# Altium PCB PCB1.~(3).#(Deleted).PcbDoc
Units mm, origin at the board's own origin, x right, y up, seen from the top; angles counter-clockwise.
Board outline 33.19 x 35.73 mm, 2 copper layers (Top Layer, Bottom Layer); 37 components, 26 nets, 150 pads, 0 vias.
Unrouted connection lines stored in the file: 81.
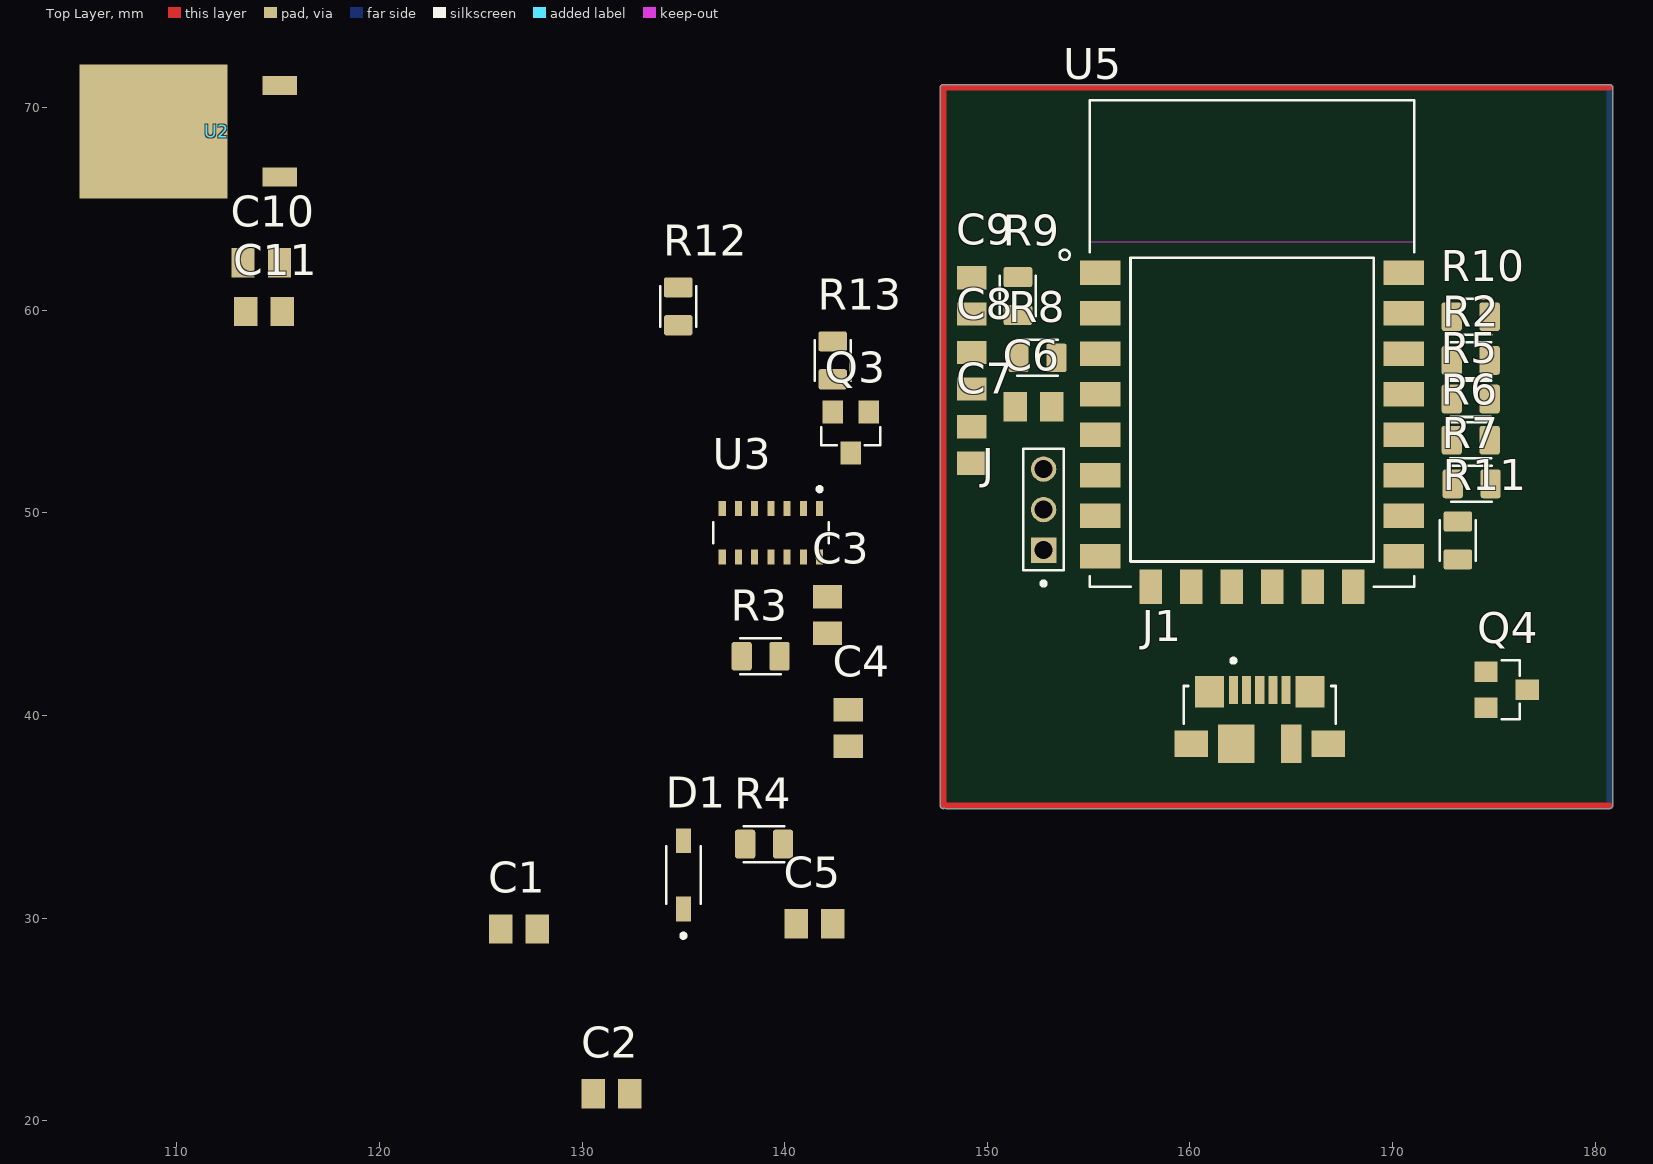
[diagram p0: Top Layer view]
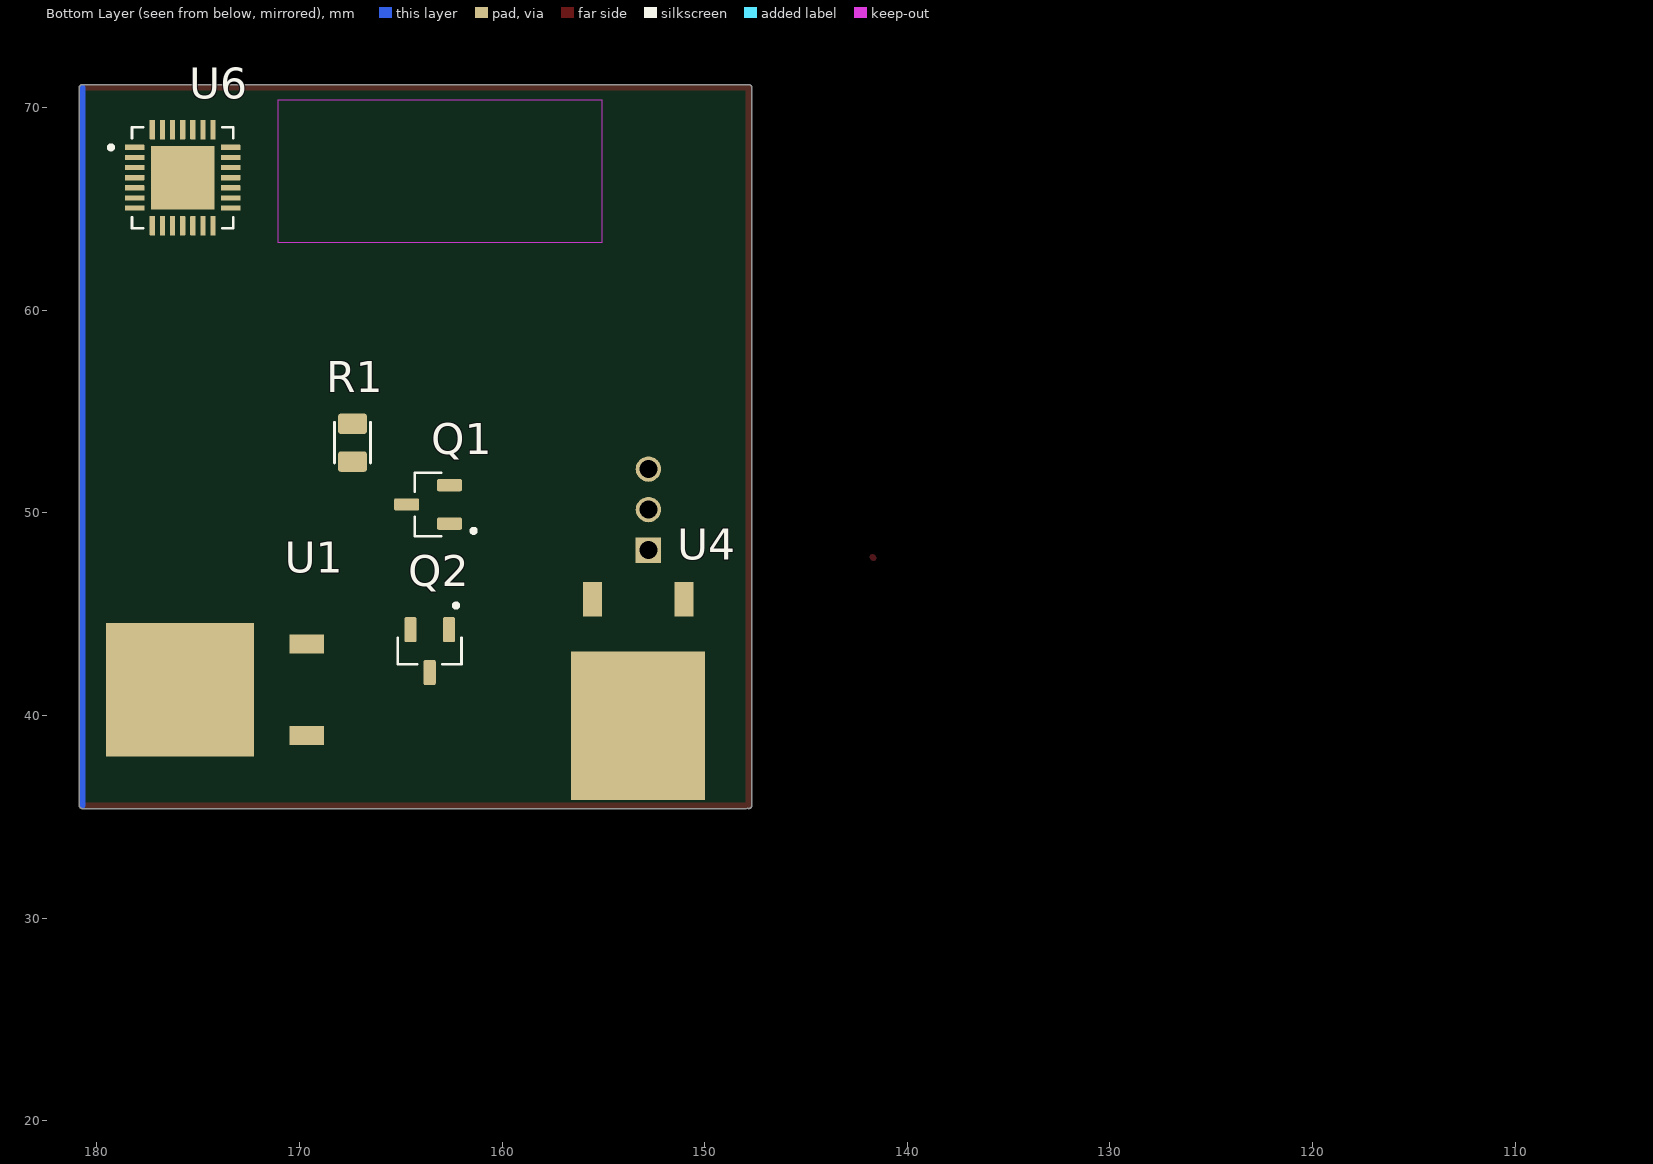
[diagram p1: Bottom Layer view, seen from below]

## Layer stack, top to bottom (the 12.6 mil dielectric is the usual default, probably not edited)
Top Solder: solder mask 0.0102, Solder Resist, Dk 3.5
Top Layer: signal copper 0.0356
Dielectric 1: dielectric 0.32, FR-4, Dk 4.8
Bottom Layer: signal copper 0.0356
Bottom Solder: solder mask 0.0102, Solder Resist, Dk 3.5

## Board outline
147.678,35.56 147.678,70.434 147.678,70.993 cw(c147.828,70.993) 147.828,71.143 180.721,71.143 cw(c180.721,70.993) 180.871,70.993 180.871,35.56 cw(c180.721,35.56) 180.721,35.41 147.955,35.41 147.892,35.424 cw(c147.828,35.56)

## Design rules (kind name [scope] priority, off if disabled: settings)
Clearance [All] p1: gap=0.254 ignorepadtopadclearanceinfootprint=FALSE except(0: Arc-Hole Track-Hole SMDPad-Hole THPad-Hole Via-Hole Fill-Hole Poly-Hole Region-Hole Text-Hole)
PolygonConnect [All] p1: connectstyle=Relief reliefconductorwidth=0.254 reliefentries=4 polygonreliefangle="90 Angle" airgapwidth=0.254
RoutingVias [All] p1: holewidth=0.711 width=1.27 viastyle="Through Hole" minholewidth=0.711 minwidth=1.27 maxholewidth=0.711 maxwidth=1.27
SolderMaskExpansion [All] p1: expansion=0.102 istentingtop=FALSE
Width [All] p1: maxlimit=0.254 minlimit=0.254 preferedwidth=0.254
30 further rules are at their usual default settings.

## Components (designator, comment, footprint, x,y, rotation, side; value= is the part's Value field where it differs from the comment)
C1 "1uF" CAPC2012X140N 126.884,29.464 r180 top
C2 "47uF" CAPC2012X140N 131.456,21.336 r0 top
C3 "0.1uF" CAPC2012X140N 142.113,44.969 r270 top
C4 "1uF" CAPC2012X140N 143.129,39.381 r90 top
C5 "10uF" CAPC2012X140N 141.478,29.718 r180 top
C6 "10uF" CAPC2012X140N 152.284,55.245 r180 top
C7 "10uF" CAPC2012X140N 149.225,53.351 r270 top
C8 "100nF" CAPC2012X140N 149.225,57.023 r90 top
C9 "100nF" CAPC2012X140N 149.225,60.717 r90 top
C10 "100nF" CAPC2012X140N 114.162,62.357 r0 top
C11 "10uF" CAPC2012X140N 114.3,59.944 r0 top
D1 "1N5819HW-7-F" SOD3715X145N 135.001,32.131 r90 top
J "2355186-3" TE_2355186-3 152.781,48.165 r90 top
J1 "47346-0001" MOLEX_47346-0001 163.449,38.608 r0 top
Q1 "BSS138" SOT95P240X111-3N 163.659,50.419 r0 bottom
Q2 "BSS138" SOT95P240X111-3N 163.576,43.18 r270 bottom
Q3 "SMD-TRANSISTORS-NPN-25V-500MW(SOT-23)" SOT-23 143.256,53.975 r180 top
Q4 "SMD-TRANSISTORS-NPN-25V-500MW(SOT-23)" SOT-23 175.641,41.275 r270 top
R1 "10K" RESC2012X65N 167.386,53.467 r270 bottom
R2 "10K" RESC2012X65N 173.863,57.531 r0 top
R3 "10K" RESC2012X65N 138.811,42.926 r0 top
R4 "10K" RESC2012X65N 138.984,33.655 r180 top
R5 "10K" RESC2012X65N 173.863,55.626 r0 top
R6 "12K" RESC2012X65N 173.863,53.594 r0 top
R7 "10K" RESC2012X65N 173.909,51.435 r0 top
R8 "10K" RESC2012X65N 152.481,57.658 r180 top
R9 "10K" RESC2012X65N 151.511,60.706 r270 top
R10 "470" RESC2012X65N 173.863,59.69 r0 top
R11 "10K" RESC2012X65N 173.228,48.641 r270 top
R12 "12K" RESC2012X65N 134.747,60.198 r90 top
R13 "12K" RESC2012X65N 142.367,57.531 r90 top
U1 "LF33CDT-TR" TO228P972X240-3N 175.743,41.275 r90 bottom
U2 "LF33CDT-TR" TO228P972X240-3N 108.991,68.834 r90 top
U3 "MAX30102EFD+T" XDCR_MAX30101EFD+ 139.319,49.022 r270 top
U4 "LF33CDT-TR" TO228P972X240-3N 153.289,39.649 r0 bottom
U5 "ESP8266-12E/ESP-12E" XCVR_ESP8266-12E/ESP-12E 163.068,54.864 r0 top
U6 "CP2102" QFN50P500X500X100-29N 175.768,66.548 r180 bottom

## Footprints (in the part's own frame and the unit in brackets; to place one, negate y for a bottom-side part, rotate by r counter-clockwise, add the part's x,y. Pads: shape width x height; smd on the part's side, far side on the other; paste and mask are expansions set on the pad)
CAPC2012X140N [mm]
  rect 1.15x1.45 smd: 1(-0.9,0) 2(0.9,0)
  body extent -1,-0.63 1,0.63, height 0.94
MOLEX_47346-0001 [mm]
  rect 0.45x1.38 smd: 1(-1.3,2.66) 2(-0.65,2.66) 3(0,2.66) 4(0.65,2.66) 5(1.3,2.66)
  rect 1.425x1.55 smd: S1(-2.488,2.575) S2(2.488,2.575)
  rect 1.65x1.3 smd: S3(-3.375,0) S6(3.375,0)
  rect 1.8x1.9 smd: S4(-1.15,0)
  rect 1x1.9 smd: S5(1.55,0)
  silkscreen extent -3.75,1 3.75,4.2, body extent -4.18,-2.93 4.18,2.5, height 2.7
QFN50P500X500X100-29N [mm]
  rrect25% 0.97x0.26 smd: 1(-2.37,1.5) 2(-2.37,1) 3(-2.37,0.5) 4(-2.37,0) 5(-2.37,-0.5) 6(-2.37,-1) 7(-2.37,-1.5) 15(2.37,-1.5) 16(2.37,-1) 17(2.37,-0.5) 18(2.37,0) 19(2.37,0.5) 20(2.37,1) 21(2.37,1.5)
  rrect25% 0.26x0.97 smd: 8(-1.5,-2.37) 9(-1,-2.37) 10(-0.5,-2.37) 11(0,-2.37) 12(0.5,-2.37) 13(1,-2.37) 14(1.5,-2.37) 22(1.5,2.37) 23(1,2.37) 24(0.5,2.37) 25(0,2.37) 26(-0.5,2.37) 27(-1,2.37) 28(-1.5,2.37)
  rect 3.15x3.15 smd paste-0.575: 29(0,0)
  silkscreen extent -3.64,-2.5 2.5,2.5
RESC2012X65N [mm]
  rrect25% 1x1.42 smd: 1(-0.935,0) 2(0.935,0)
  silkscreen extent -1,-0.89 1,0.89, body extent -1,-0.63 1,0.63, height 0.6
SOD3715X145N [mm]
  rect 1.21x0.73 smd: A(1.68,0) C(-1.68,0)
  silkscreen extent -3.1,-0.85 1.42,0.85, body extent -1.83,-0.77 1.83,0.77, height 0.8
SOT95P240X111-3N [mm]
  rrect25% 1.23x0.6 smd: 1(-1.06,0.95) 2(-1.06,-0.95) 3(1.06,0)
  silkscreen extent -2.35,-1.57 0.65,1.57, body extent -1.2,-1.46 1.2,1.46, height 1.2
SOT-23 [mil]
  rect 40x45 smd: 1(-35,-40) 2(35,-40) 3(0,40)
  silkscreen extent -58,-10 58,25, body extent -57,-51 57,51, height 55
TE_2355186-3 [mm]
  rect 1.25x1.25 hole 0.9: 1(0,0)
  round 1.25 hole 0.9: 2(2,0) 3(4,0)
  silkscreen extent -1.75,-1 5,1
TO228P972X240-3N [mil]
  rect 37x67 smd: 1(-89,-240) 3(89,-240)
  rect 260x288 smd: 2(0,6)
  body extent -186,-128 197,128, height 94
XCVR_ESP8266-12E/ESP-12E [mm]
  rect 2x1.2 smd: 1(-7.5,7) 2(-7.5,5) 3(-7.5,3) 4(-7.5,1) 5(-7.5,-1) 6(-7.5,-3) 7(-7.5,-5) 8(-7.5,-7) 15(7.5,-7) 16(7.5,-5) 17(7.5,-3) 18(7.5,-1) 19(7.5,1) 20(7.5,3) 21(7.5,5) 22(7.5,7)
  rect 1.1x1.7 smd: 9(-5,-8.5) 10(-3,-8.5) 11(-1,-8.5) 12(1,-8.5) 13(3,-8.5) 14(5,-8.5)
  Keep-Out Layer region: 8,8.51 -8.009,8.51 -8.009,15.5 8,15.5
  Keep-Out Layer region: 8,8.51 -8.009,8.51 -8.009,15.5 8,15.5
  silkscreen extent -9.5,-8.5 8,15.5, body extent -8,-12 8,12, height 3
XDCR_MAX30101EFD+ [mm]
  rect 0.75x0.35 smd: 1(-1.2,2.4) 2(-1.2,1.6) 3(-1.2,0.8) 4(-1.2,0) 5(-1.2,-0.8) 6(-1.2,-1.6) 7(-1.2,-2.4) 8(1.2,-2.4) 9(1.2,-1.6) 10(1.2,-0.8) 11(1.2,0) 12(1.2,0.8) 13(1.2,1.6) 14(1.2,2.4)
  silkscreen extent -2.25,-2.85 0.51,2.85

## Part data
C1 C2 C3 C4 C5 C6 C7 C8 C9 C10 C11: library part LD051C121KAB2A, "Ceramic Capacitor", Package="0805 AVX"
D1: "Diode Schottky 40 V 1A Surface Mount SOD-123", Package="SOD-123 Fairchild Semiconductor"
J: "Pin 3P,2MM,BRK HDR,SRVT,2.8,0.76AU,BOX 3 POS", Package=None
J1: "USB - micro B USB 2.0 Receptacle Connector 5 Position Surface Mount, Right Angle", Package=None
Q1 Q2: "N-Channel 50 V 220mA (Ta) 350mW (Ta) Surface Mount SOT-23-3", Package="SOT-23-3 Motorola"
Q3 Q4: "Bipolar (BJT) Transistor NPN 25 V 500 mA 150MHz 300 mW Surface Mount SOT-23", Package=None
R1 R2 R3 R4 R5 R6 R7 R8 R9 R10 R11 R12 R13: library part 2-2176053-0, "RES 0.33 OHM 1% 1/4W 0805", Package=0805, Power_Rating=".25 W", Resistance=.33, Tolerance=1%
U1 U2 U4: "Linear Voltage Regulator IC Positive Fixed 1 Output 500mA DPAK", Package="TO-252-3 STMicroelectronics"
U3: "Pulse Oximeter and Heart Rate Sensor Digital Output", Package=None
U5: "This WiFi module has a 32-bit MCU micro and clock speeds supporting 80 MHz or 160 MHz. Supports the RTOS and integrated Wi-Fi MAC/BB/RF/PA/LNA, and has an on-board antenna.", Package=None
U6: "CP2102N USB 2.0 to UART (RS232) Bridge Interface Evaluation Board", Package="WFQFN-20 Silicon Labs"

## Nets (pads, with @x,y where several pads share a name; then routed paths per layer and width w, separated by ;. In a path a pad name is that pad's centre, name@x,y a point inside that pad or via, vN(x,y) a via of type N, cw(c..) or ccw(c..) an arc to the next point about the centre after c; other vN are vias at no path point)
1V8: C4.2 U2.3 U3.11
3V3: C2.2 C3.2 Q1.1 Q2.1 R1.2 R3.2 R4.2 U1.3 U2.1
3V3_ESP: C6.2 C7.1 C8.1 J.1 R6.2 R7.2 R8.2 R9.2 U4.3 U5.8 U6.6 U6.7
ASCL: Q1.3 R2.1 U5.20
ASDA: Q2.3 R5.1 U5.19
AVCC: C1.2 C5.2 D1.C R2.2 R5.2 U1.1 U4.1
BSCL: Q1.2 R1.1 U3.2
BSDA: Q2.2 R4.1 U3.3
D_N: J1.2 U6.5
D_P: J1.3 U6.4
DTR: Q4.2 R12.1 U6.28
EN: R8.1 U5.3
GND: C1.1 C2.1 C3.1 C4.1 C5.1 C6.1 C7.2 C8.2 C9.1 C10.1 C11.1 J1.5 J.3 R11.2 U1.2 U2.2 U3.4 U3.12 U4.2 U5.15 U6.3 U6.29
GPIO0: Q4.3 R6.1 U5.18
GPIO2: R7.1 U5.17
GPIO13: J.2 U5.7
GPIO15: R11.1 U5.16
INT: R3.1 U3.13
NetQ3_1: Q3.1 R12.2
NetQ4_1: Q4.1 R13.2
NetR10_2: R10.2 U6.26
nRST: C9.2 Q3.3 R9.1 U5.1
RTS: Q3.2 R13.1 U6.24
RXD: R10.1 U5.21
TXD: U5.22 U6.25
VDDUSB: C10.2 C11.2 D1.A J1.1 U6.8
pads on no net: J1.4 J1.S1 J1.S2 J1.S3 J1.S4 J1.S5 J1.S6 U3.1 U3.5 U3.6 U3.7 U3.8 U3.9 U3.10 U3.14 U5.2 U5.4 U5.5 U5.6 U5.9 U5.10 U5.11 U5.12 U5.13 U5.14 U6.1 U6.2 U6.9 U6.10 U6.11 U6.12 U6.13 U6.14 U6.15 U6.16 U6.17 U6.18 U6.19 U6.20 U6.21 U6.22 U6.23 U6.27
copper on no net: | length 136.6
  Top Layer w0.3: 141.67,47.773 141.719,47.822 ; 147.828,35.56 147.828,70.434 147.828,70.993 148.387,70.993 180.721,70.993 ; 147.955,35.56 180.721,35.56
  Bottom Layer w0.3: 180.721,35.56 180.721,70.993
